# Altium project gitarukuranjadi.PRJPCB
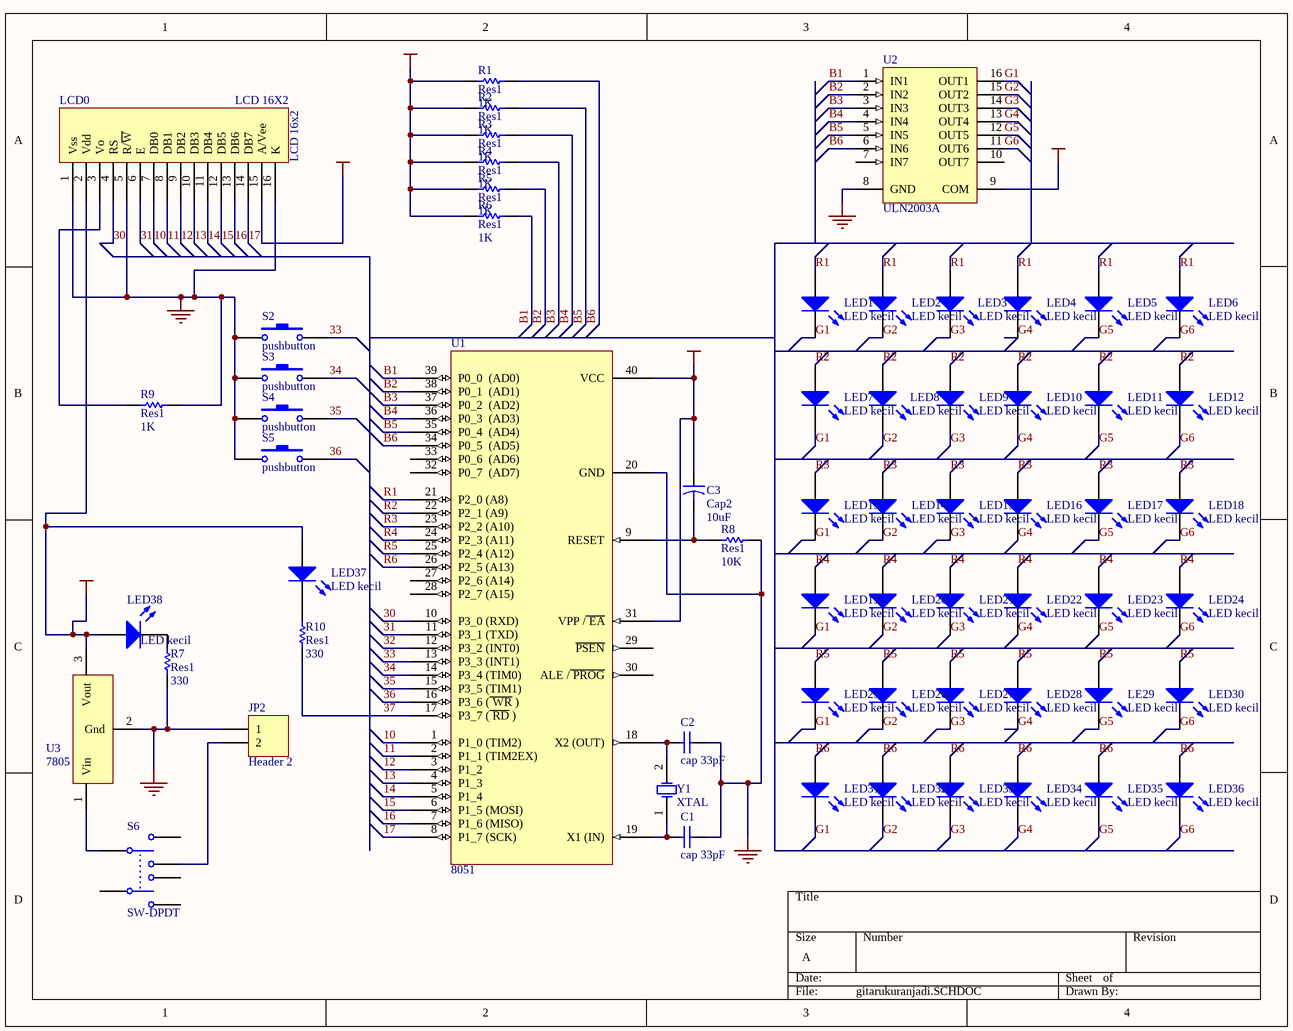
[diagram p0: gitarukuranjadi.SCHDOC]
1 sheet, 62 parts. Net scope: global (net labels, ports and power ports of the same name join across sheets).
Board file: gitarukuranjadi.PCBDOC

## Sheet gitarukuranjadi.SCHDOC
size A

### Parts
C1  cap 33pF  [cap 22/33uF]
C2  cap 33pF  [cap 22/33uF]
C3  Cap2  value 10uF  [CAPR5-4X5]
JP2  Header 2  [HDR1X2]
LCD0  LCD 16X2  [LCD 16X2]
LE29  LED kecil  [LED kecil]
LED1  LED kecil  [LED kecil]
LED2  LED kecil  [LED kecil]
LED3  LED kecil  [LED kecil]
LED4  LED kecil  [LED kecil]
LED5  LED kecil  [LED kecil]
LED6  LED kecil  [LED kecil]
LED7  LED kecil  [LED kecil]
LED8  LED kecil  [LED kecil]
LED9  LED kecil  [LED kecil]
LED10  LED kecil  [LED kecil]
LED11  LED kecil  [LED kecil]
LED12  LED kecil  [LED kecil]
LED13  LED kecil  [LED kecil]
LED14  LED kecil  [LED kecil]
LED15  LED kecil  [LED kecil]
LED16  LED kecil  [LED kecil]
LED17  LED kecil  [LED kecil]
LED18  LED kecil  [LED kecil]
LED19  LED kecil  [LED kecil]
LED20  LED kecil  [LED kecil]
LED21  LED kecil  [LED kecil]
LED22  LED kecil  [LED kecil]
LED23  LED kecil  [LED kecil]
LED24  LED kecil  [LED kecil]
LED25  LED kecil  [LED kecil]
LED26  LED kecil  [LED kecil]
LED27  LED kecil  [LED kecil]
LED28  LED kecil  [LED kecil]
LED30  LED kecil  [LED kecil]
LED31  LED kecil  [LED kecil]
LED32  LED kecil  [LED kecil]
LED33  LED kecil  [LED kecil]
LED34  LED kecil  [LED kecil]
LED35  LED kecil  [LED kecil]
LED36  LED kecil  [LED kecil]
LED37  LED kecil  [LED kecil]
LED38  LED kecil  [LED kecil]
R1  Res1  value 1K  [AXIAL-0.3]
R2  Res1  value 1K  [AXIAL-0.3]
R3  Res1  value 1K  [AXIAL-0.3]
R4  Res1  value 1K  [AXIAL-0.3]
R5  Res1  value 1K  [AXIAL-0.3]
R6  Res1  value 1K  [AXIAL-0.3]
R7  Res1  value 330  [AXIAL-0.3]
R8  Res1  value 10K  [AXIAL-0.3]
R9  Res1  value 1K  [AXIAL-0.3]
R10  Res1  value 330  [AXIAL-0.3]
S2  pushbutton  [pushbutton]
S3  pushbutton  [pushbutton]
S4  pushbutton  [pushbutton]
S5  pushbutton  [pushbutton]
S6  SW-DPDT  [DPDT-6]
U1  8051  [8051 40 pin]
U2  ULN2003A  [A16]
U3  7805  [78XX/79XX]
Y1  XTAL  [XTAL]

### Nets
GND: C1.2 C2.2 JP2.1 LCD0.1(Vss) LCD0.5(R/~{W}) LCD0.16(K) R7.1 R8.2 R9.2 S2.1 S3.1 S4.1 S5.1 U1.20(GND) U2.8(GND) U3.2(Gnd)
VCC: C3.1 LCD0.2(Vdd) LCD0.15(A/Vee) LED37.1(A) LED38.1(A) R1.1 R2.1 R3.1 R4.1 R5.1 R6.1 U1.31(VPP_/~{_EA}) U1.40(VCC) U2.9(COM) U3.3(Vout)
10: LCD0.7(DB0) U1.1(P1_0_(TIM2))
11: LCD0.8(DB1) U1.2(P1_1_(TIM2EX))
12: LCD0.9(DB2) U1.3(P1_2)
13: LCD0.10(DB3) U1.4(P1_3)
14: LCD0.11(DB4) U1.5(P1_4)
15: LCD0.12(DB5) U1.6(P1_5_(MOSI))
16: LCD0.13(DB6) U1.7(P1_6_(MISO))
17: LCD0.14(DB7) U1.8(P1_7_(SCK))
30: LCD0.4(RS) U1.10(P3_0_(RXD))
31: LCD0.6(E) U1.11(P3_1_(TXD))
32: U1.12(P3_2_(INT0))
33: S2.2 U1.13(P3_3_(INT1))
34: S3.2 U1.14(P3_4_(TIM0))
35: S4.2 U1.15(P3_5_(TIM1))
36: S5.2 U1.16(P3_6_(~{_WR}_))
37: R10.1 U1.17(P3_7_(~{_RD}_))
B1: R6.2 U1.39(P0_0__(AD0)) U2.1(IN1)
B2: R5.2 U1.38(P0_1__(AD1)) U2.2(IN2)
B3: R4.2 U1.37(P0_2__(AD2)) U2.3(IN3)
B4: R3.2 U1.36(P0_3__(AD3)) U2.4(IN4)
B5: R2.2 U1.35(P0_4__(AD4)) U2.5(IN5)
B6: R1.2 U1.34(P0_5__(AD5)) U2.6(IN6)
G1: LED1.2(K) LED7.2(K) LED13.2(K) LED19.2(K) LED25.2(K) LED31.2(K) U2.16(OUT1)
G2: LED2.2(K) LED8.2(K) LED14.2(K) LED20.2(K) LED26.2(K) LED32.2(K) U2.15(OUT2)
G3: LED3.2(K) LED9.2(K) LED15.2(K) LED21.2(K) LED27.2(K) LED33.2(K) U2.14(OUT3)
G4: LED4.2(K) LED10.2(K) LED16.2(K) LED22.2(K) LED28.2(K) LED34.2(K) U2.13(OUT4)
G5: LE29.2(K) LED5.2(K) LED11.2(K) LED17.2(K) LED23.2(K) LED35.2(K) U2.12(OUT5)
G6: LED6.2(K) LED12.2(K) LED18.2(K) LED24.2(K) LED30.2(K) LED36.2(K) U2.11(OUT6)
R1: LED1.1(A) LED2.1(A) LED3.1(A) LED4.1(A) LED5.1(A) LED6.1(A) U1.21(P2_0_(A8))
R2: LED7.1(A) LED8.1(A) LED9.1(A) LED10.1(A) LED11.1(A) LED12.1(A) U1.22(P2_1_(A9))
R3: LED13.1(A) LED14.1(A) LED15.1(A) LED16.1(A) LED17.1(A) LED18.1(A) U1.23(P2_2_(A10))
R4: LED19.1(A) LED20.1(A) LED21.1(A) LED22.1(A) LED23.1(A) LED24.1(A) U1.24(P2_3_(A11))
R5: LE29.1(A) LED25.1(A) LED26.1(A) LED27.1(A) LED28.1(A) LED30.1(A) U1.25(P2_4_(A12))
R6: LED31.1(A) LED32.1(A) LED33.1(A) LED34.1(A) LED35.1(A) LED36.1(A) U1.26(P2_5_(A13))
NetC1_1: C1.1 U1.19(X1_(IN)) Y1.1(OSC1)
NetC2_1: C2.1 U1.18(X2_(OUT)) Y1.2(OSC2)
NetC3_2: C3.2 R8.1 U1.9(RESET)
NetJP2_2: JP2.2 S6.3
NetLCD0_3: LCD0.3(Vo) R9.1
NetLED37_2: LED37.2(K) R10.2
NetLED38_2: LED38.2(K) R7.2
NetS6_1: S6.1 U3.1(Vin)

Not connected (* = marked no-connect by the designer): S6 2 4 5 6; U1 27(P2_6_(A14)) 28(P2_7_(A15)) 29(~{PSEN}) 30(ALE_/~{_PROG}) 32(P0_7__(AD7)) 33(P0_6__(AD6)); U2 7(IN7) 10(OUT7)

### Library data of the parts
C1 C2 = cap 22/33uF
C3 = Cap2: Capacitor
JP2 = Header 2: Header, 2-Pin
R1-R10 = Res1: Resistor
S6 = SW-DPDT: Double-Pole, Double-Throw Switch
U1 = 8051 40 pin
U2 = ULN2003A: High-Voltage, High-Current Darlington Array; PackageDocument: 1998
U3 = 7805/7809/7812/7905/7909/7912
